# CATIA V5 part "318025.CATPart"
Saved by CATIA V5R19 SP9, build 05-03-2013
Part number: 318025
Source: Unknown
Bounding box of the stored display mesh (mm): x -86 to 342.005, y -364 to 364, z 381.245 to 440
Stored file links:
  D:\16-SIL\kale oto\R19_V1\318025.CATPart
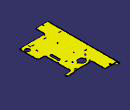
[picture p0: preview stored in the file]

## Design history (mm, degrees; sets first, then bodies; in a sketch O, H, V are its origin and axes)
Set1
  Line1 "Project.1": stored without definition
Body1 "120\\5\\MANIFOLD_SOLID_BREP #16656" (main body)
  Solid1: solid without history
